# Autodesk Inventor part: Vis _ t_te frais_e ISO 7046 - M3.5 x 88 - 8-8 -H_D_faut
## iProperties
Created: 2011-10
Part Number: Vis _ t_te frais_e ISO 7046 - M3.5 x 88 - 8-8 -H_D_faut
Document SubType Name: Modeling
Designer: Bruno
Author: Bruno
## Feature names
1. Base1
